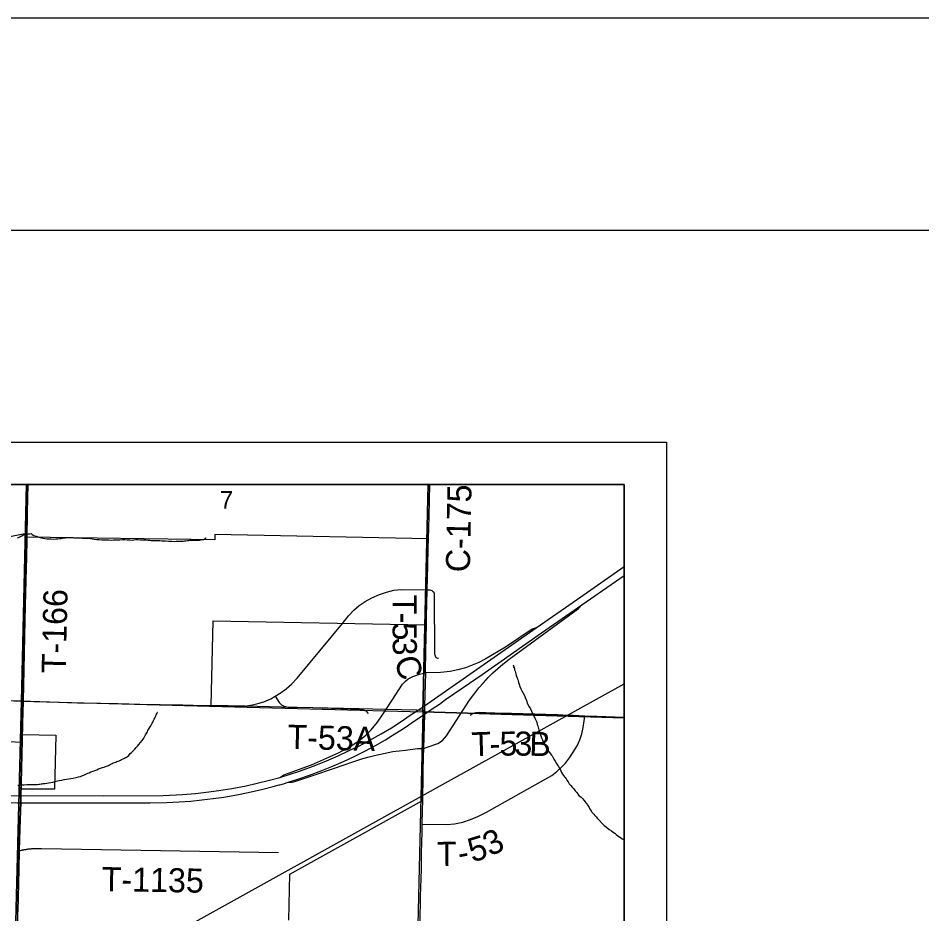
# Model space of a CAD drawing. Extents: x 0 to 34, y 0 to 22.
# Drawn here: x 7.471 to 9.602, y 19.887 to 22 of the extents above; entities that cross this region are included whole.
import ezdxf

# ---------------------------------------------------------------- set-up
doc = ezdxf.new("R2010")
doc.units = 0
for name, color, linetype in [('Default', 7, 'Continuous'), ('GM_X_City_Street', 7, 'Continuous'), ('GM_X_County_Road', 7, 'Continuous'), ('GM_X_County_Road_Text', 7, 'Continuous'), ('GM_X_Interchange_Ramps', 7, 'Continuous'), ('GM_X_Minor_River', 7, 'Continuous'), ('GM_X_Rail_Line', 7, 'Continuous'), ('GM_X_Section', 7, 'Continuous'), ('GM_X_Section_Text', 7, 'Continuous'), ('GM_X_State_Route', 7, 'Continuous'), ('GM_X_Township_Road', 7, 'Continuous'), ('GM_X_Township_Road_Text', 7, 'Continuous'), ('GM_X_US_Route', 7, 'Continuous'), ('SH_Border', 7, 'Continuous'), ('SH_Cut_Line', 7, 'Continuous'), ('SH_Data', 7, 'Continuous')]:
    doc.layers.add(name, color=color, linetype=linetype)

msp = doc.modelspace()

# ---------------------------------------------------------------- linework, layer by layer
at = {"layer": 'Default'}
for points in [[(7.4909, 20.9), (6.494, 20.9), (6.4853, 20.433), (7.4792, 20.3884)], [(8.4378, 20.9), (7.4909, 20.9), (7.4792, 20.3884), (8.425, 20.3637)], [(8.9, 20.3497), (8.9, 20.9), (8.4378, 20.9), (8.425, 20.3637)], [(8.9, 19.3466), (8.9, 20.3497), (8.425, 20.3637), (8.4018, 19.3591)]]:
    msp.add_lwpolyline(points, close=True, dxfattribs=at)
for points in [[(8.1092, 19.8726), (8.1117, 19.9804), (8.4242, 20.1544), (8.4244, 20.1687), (8.4248, 20.1996), (8.4253, 20.2288), (8.4259, 20.2469), (8.4287, 20.3585), (8.4289, 20.3671), (8.4123, 20.3673), (8.3381, 20.3691), (8.2755, 20.3708), (8.0918, 20.3747), (8.0063, 20.3766), (7.9263, 20.3784), (7.9309, 20.578), (8.4317, 20.5692), (8.4382, 20.7718), (7.935, 20.7816), (7.9348, 20.7695), (7.491, 20.7754), (7.491, 20.7842), (7.419, 20.7702)], [(7.3521, 20.3956), (7.4824, 20.3891), (7.4824, 20.3889), (7.4808, 20.31), (7.5596, 20.3083), (7.5569, 20.1815), (7.4776, 20.1816), (7.4779, 20.1915), (7.4782, 20.2008), (7.4786, 20.2232), (7.4804, 20.2916), (7.3464, 20.2972)]]:
    msp.add_lwpolyline(points, dxfattribs=at)
at = {"layer": 'GM_X_City_Street'}
msp.add_lwpolyline([(7.4738, 20.0361), (7.4792, 20.0373), (7.4804, 20.0376), (7.4816, 20.0379), (7.4829, 20.0381), (7.4841, 20.0384), (7.4853, 20.0386), (7.4865, 20.0388), (7.4877, 20.039), (7.4889, 20.0392), (7.4895, 20.0393), (7.4908, 20.0395), (7.492, 20.0397), (7.4932, 20.0399), (7.4944, 20.0401), (7.4957, 20.0402), (7.4969, 20.0403), (7.4981, 20.0405), (7.4993, 20.0406), (7.5006, 20.0407), (7.5018, 20.0408), (7.503, 20.0409), (7.5043, 20.041), (7.5055, 20.0411), (7.5061, 20.0411), (7.5073, 20.0412), (7.508, 20.0412), (7.5092, 20.0413), (7.5098, 20.0413), (7.5111, 20.0413), (7.5123, 20.0413), (7.5129, 20.0413), (7.5141, 20.0414), (7.5154, 20.0414), (7.5166, 20.0413), (7.5172, 20.0413), (7.5185, 20.0413), (7.5197, 20.0413), (7.5209, 20.0412), (7.5216, 20.0412), (7.5228, 20.0412), (7.5234, 20.0411), (7.5246, 20.0411), (7.5259, 20.041), (7.6676, 20.0386), (8.0853, 20.0316)], dxfattribs=at)
at = {"layer": 'GM_X_County_Road'}
for points in [[(8.4388, 20.7716), (8.44, 20.8244), (8.4418, 20.9)], [(8.4359, 20.6517), (8.4373, 20.7087), (8.4383, 20.7498), (8.4388, 20.7716)], [(8.2356, 20.5721), (8.2502, 20.5897), (8.2626, 20.6033), (8.2751, 20.6142), (8.2896, 20.6241), (8.3047, 20.6326), (8.3228, 20.6405), (8.3395, 20.6461), (8.357, 20.6504), (8.3744, 20.6523), (8.4359, 20.6517)], [(8.434, 20.5677), (8.4344, 20.5875), (8.4359, 20.6517)], [(7.9262, 20.3785), (7.9933, 20.3768), (8.0098, 20.3781), (8.0236, 20.3804), (8.0364, 20.3834), (8.0502, 20.3876), (8.0666, 20.3942), (8.0772, 20.4005), (8.091, 20.409), (8.1031, 20.4179), (8.1156, 20.4291), (8.1288, 20.4432), (8.2356, 20.5721)], [(8.4316, 20.4557), (8.4326, 20.5092), (8.434, 20.5677)], [(7.3527, 20.3949), (7.3686, 20.3941), (7.4177, 20.3919), (7.4532, 20.3906), (7.478, 20.3895), (7.4826, 20.3893)], [(7.4826, 20.3893), (7.5004, 20.3887), (7.5445, 20.3869), (7.5873, 20.3859), (7.611, 20.3852), (7.6248, 20.3848)], [(7.6248, 20.3848), (7.7061, 20.3829), (7.7577, 20.3818), (7.8062, 20.3809), (7.859, 20.3798), (7.9081, 20.3789), (7.9262, 20.3785)]]:
    msp.add_lwpolyline(points, dxfattribs=at)
at = {"layer": 'GM_X_Interchange_Ramps'}
for points in [[(8.4267, 20.2774), (8.4402, 20.2821), (8.4609, 20.2893), (8.4721, 20.2959), (8.4813, 20.3068), (8.5355, 20.3913), (8.5454, 20.4047), (8.5575, 20.4199), (8.5681, 20.4324), (8.5792, 20.4445), (8.5908, 20.456), (8.6019, 20.4662), (8.6141, 20.4764), (8.6289, 20.4876), (8.7922, 20.6077), (8.8006, 20.6163)], [(8.6929, 20.5615), (8.6832, 20.5587), (8.6202, 20.5162), (8.572, 20.4879), (8.5575, 20.48), (8.5421, 20.4735), (8.5257, 20.4675), (8.5076, 20.4626), (8.4895, 20.459), (8.4668, 20.4564), (8.4316, 20.4557)]]:
    msp.add_lwpolyline(points, dxfattribs=at)
at = {"layer": 'GM_X_Minor_River'}
for points in [[(7.4697, 20.774), (7.4716, 20.7747), (7.4747, 20.7762), (7.4774, 20.778), (7.4797, 20.7791), (7.4832, 20.7812), (7.4863, 20.7823), (7.4909, 20.7829), (7.4943, 20.7836), (7.4985, 20.7838)], [(7.4985, 20.7838), (7.5015, 20.7841), (7.5037, 20.7822), (7.5082, 20.7798), (7.5131, 20.7777), (7.5184, 20.7764), (7.5229, 20.7751), (7.5263, 20.7743), (7.5289, 20.7735), (7.5339, 20.7726), (7.5384, 20.772), (7.5429, 20.7715), (7.5483, 20.7714), (7.5539, 20.7712), (7.5597, 20.7714), (7.5642, 20.7717), (7.5684, 20.7723), (7.5726, 20.7726), (7.5757, 20.7733), (7.5791, 20.7739), (7.5829, 20.7742), (7.5958, 20.7746), (7.5996, 20.7745), (7.6034, 20.7744), (7.6076, 20.7742), (7.6129, 20.7741), (7.6178, 20.7739), (7.6231, 20.7734), (7.6281, 20.7733), (7.6326, 20.7735), (7.6372, 20.773), (7.6413, 20.7725), (7.6455, 20.7716), (7.65, 20.7711), (7.6561, 20.7702), (7.6622, 20.77), (7.6682, 20.7694), (7.6739, 20.7693), (7.6796, 20.7691), (7.6849, 20.769), (7.6902, 20.7688), (7.696, 20.7694), (7.7043, 20.7695), (7.7108, 20.7697), (7.7172, 20.7699), (7.7222, 20.7702), (7.7282, 20.7696), (7.7343, 20.7691), (7.74, 20.7689), (7.7438, 20.7692), (7.7488, 20.7702), (7.7529, 20.77), (7.7594, 20.7695), (7.7662, 20.7693), (7.7723, 20.7691), (7.7776, 20.7689), (7.7818, 20.7684), (7.7844, 20.768), (7.7882, 20.7675), (7.7909, 20.7674), (7.7939, 20.7677), (7.7996, 20.7676), (7.8049, 20.7674), (7.8095, 20.7673), (7.8129, 20.7672), (7.8159, 20.7667), (7.8182, 20.7666), (7.8254, 20.766), (7.8292, 20.7663), (7.8337, 20.7662), (7.8398, 20.7656), (7.8436, 20.7659), (7.8474, 20.7662), (7.8516, 20.7661), (7.8565, 20.7663), (7.8603, 20.7662), (7.8634, 20.7669), (7.8668, 20.7671), (7.8702, 20.7678), (7.8733, 20.7681), (7.876, 20.7684), (7.8786, 20.7683), (7.8813, 20.7686), (7.884, 20.7689), (7.8862, 20.7689), (7.89, 20.7687), (7.8919, 20.7687), (7.8942, 20.7686), (7.8965, 20.7689), (7.8988, 20.7689), (7.9018, 20.7692), (7.9053, 20.7698), (7.9079, 20.7705), (7.9102, 20.7716), (7.913, 20.7734), (7.9137, 20.7738), (7.9137, 20.7734)], [(8.6381, 20.4746), (8.6405, 20.4681), (8.6395, 20.4708), (8.6405, 20.4681), (8.6416, 20.4658), (8.6419, 20.4627), (8.6429, 20.4596), (8.6436, 20.4566), (8.6446, 20.4531), (8.6457, 20.4497), (8.6467, 20.4455), (8.6481, 20.4428), (8.6492, 20.4401), (8.6502, 20.4366), (8.6513, 20.4332), (8.6523, 20.4286), (8.654, 20.4236), (8.6562, 20.4182), (8.659, 20.4128), (8.6619, 20.4074), (8.6648, 20.4024), (8.667, 20.3978), (8.6698, 20.3904), (8.6726, 20.3828), (8.6758, 20.3758), (8.6791, 20.3704), (8.6816, 20.3654), (8.6841, 20.3596), (8.6869, 20.3538), (8.6895, 20.3488), (8.6916, 20.3442), (8.6934, 20.3411), (8.6941, 20.3384), (8.6951, 20.3338), (8.6965, 20.3304), (8.6972, 20.3273), (8.6979, 20.3243), (8.6989, 20.3208), (8.7003, 20.317), (8.7017, 20.3127), (8.7034, 20.3074), (8.7056, 20.3024), (8.7077, 20.2974), (8.7095, 20.2928), (8.7113, 20.2893), (8.7127, 20.2866), (8.7138, 20.2843), (8.7145, 20.2823), (8.7163, 20.2789), (8.7196, 20.2742), (8.7232, 20.2688), (8.7265, 20.2645), (8.7291, 20.2618), (8.7305, 20.2598), (8.732, 20.2564), (8.7345, 20.2521), (8.7374, 20.2471), (8.7403, 20.2421), (8.7432, 20.2378), (8.7457, 20.2343), (8.7472, 20.2316), (8.749, 20.2285), (8.7508, 20.2247), (8.7526, 20.2208), (8.7551, 20.2169), (8.7573, 20.2138), (8.7595, 20.2107), (8.7613, 20.2084), (8.7631, 20.2057), (8.7653, 20.2026), (8.7679, 20.1983), (8.7708, 20.1941), (8.7741, 20.1902), (8.7774, 20.1859), (8.7811, 20.182), (8.7847, 20.1773), (8.7884, 20.173), (8.7928, 20.1672), (8.7987, 20.1625), (8.8024, 20.1586), (8.8053, 20.155), (8.8079, 20.1516), (8.8101, 20.1492), (8.8119, 20.1465), (8.8134, 20.1446), (8.8148, 20.1426), (8.8159, 20.1403), (8.8174, 20.1376), (8.8195, 20.1341), (8.8225, 20.1302), (8.8243, 20.1271), (8.8265, 20.1244), (8.8287, 20.1221), (8.8313, 20.1193), (8.8342, 20.1158), (8.8375, 20.1119), (8.8534, 20.0959), (8.8589, 20.0915), (8.8645, 20.0861), (8.8705, 20.0828), (8.8746, 20.0801)], [(7.6288, 20.2157), (7.6319, 20.2171), (7.635, 20.2186), (7.6388, 20.22), (7.6427, 20.2221), (7.6481, 20.2235), (7.6519, 20.2253), (7.6565, 20.227), (7.6607, 20.2288), (7.6654, 20.2306), (7.6696, 20.232), (7.6738, 20.2334), (7.6769, 20.2344), (7.6792, 20.2351), (7.6815, 20.2362), (7.6838, 20.2373), (7.6861, 20.2384), (7.6892, 20.2402), (7.6923, 20.2416), (7.6953, 20.243), (7.6984, 20.2441), (7.7011, 20.2451), (7.7038, 20.2462), (7.7065, 20.2469), (7.7088, 20.248), (7.7107, 20.2487), (7.7126, 20.2498), (7.715, 20.2512), (7.7188, 20.2526), (7.7215, 20.2541), (7.7242, 20.2559), (7.7265, 20.257), (7.7285, 20.2584), (7.7316, 20.261), (7.7335, 20.2628), (7.7355, 20.2651), (7.7382, 20.2676), (7.7414, 20.271), (7.7461, 20.2758), (7.7496, 20.2795), (7.7527, 20.2828), (7.7559, 20.2865), (7.7638, 20.2962), (7.7657, 20.2991), (7.767, 20.3018), (7.7686, 20.3044), (7.7698, 20.3066), (7.7714, 20.3096), (7.7729, 20.3115), (7.7741, 20.3137), (7.7757, 20.3163), (7.777, 20.3193), (7.7786, 20.3223), (7.7806, 20.3257), (7.7822, 20.3283), (7.7838, 20.3309), (7.7854, 20.3335), (7.787, 20.3365), (7.7886, 20.3395), (7.7902, 20.3433), (7.7918, 20.3463), (7.793, 20.3489), (7.7942, 20.3512), (7.7955, 20.3538), (7.7963, 20.356), (7.7971, 20.3579), (7.7987, 20.3605), (7.7995, 20.362), (7.7991, 20.362)], [(7.4701, 20.1906), (7.4735, 20.1909), (7.4766, 20.1912), (7.4804, 20.1915), (7.4849, 20.1917), (7.4918, 20.1919), (7.4971, 20.1921), (7.5032, 20.192), (7.5089, 20.1922), (7.5134, 20.192), (7.5165, 20.1923), (7.5195, 20.193), (7.5222, 20.1933), (7.5249, 20.1936), (7.5275, 20.1939), (7.5302, 20.1942), (7.5336, 20.1949), (7.5386, 20.1955), (7.5428, 20.1961), (7.5481, 20.1971), (7.5531, 20.1981), (7.5577, 20.1995), (7.5634, 20.2005), (7.5688, 20.2018), (7.5738, 20.2028), (7.5791, 20.2042), (7.6009, 20.2074), (7.6077, 20.2087), (7.6135, 20.21), (7.6181, 20.2111), (7.6215, 20.2125), (7.6238, 20.2132), (7.6261, 20.2146), (7.6288, 20.2157)], [(8.8746, 20.0801), (8.8783, 20.0773), (8.8816, 20.0745), (8.8846, 20.0722), (8.8879, 20.0698), (8.8916, 20.067), (8.8957, 20.0642), (8.9, 20.0615)]]:
    msp.add_lwpolyline(points, dxfattribs=at)
at = {"layer": 'GM_X_Rail_Line'}
msp.add_lwpolyline([(6.8451, 19.2922), (7.7668, 19.8007), (8.4856, 20.1997), (8.9, 20.43)], dxfattribs=at)
at = {"layer": 'GM_X_Section'}
for points in [[(6.4853, 20.433), (7.4792, 20.3884), (7.4533, 19.3812), (6.7152, 19.4245), (6.466, 19.4302)], [(7.4792, 20.3884), (8.425, 20.3637), (8.4018, 19.3591), (7.4533, 19.3812)]]:
    msp.add_lwpolyline(points, close=True, dxfattribs=at)
at = {"layer": 'GM_X_State_Route'}
for p, q in [((8.3383, 20.3685), (8.353, 20.3912)), ((8.4267, 20.2774), (8.4263, 20.2574))]:
    msp.add_line(p, q, dxfattribs=at)
for points in [[(8.353, 20.3912), (8.3774, 20.4291), (8.3843, 20.436), (8.3908, 20.4416), (8.4017, 20.4468), (8.4175, 20.4521), (8.4316, 20.4557), (8.4293, 20.3781), (8.4291, 20.3665), (8.4289, 20.358), (8.4267, 20.2774)], [(8.0884, 20.2091), (8.0972, 20.2153), (8.1084, 20.219), (8.1626, 20.2387), (8.1913, 20.2512), (8.2261, 20.2666), (8.2554, 20.2824), (8.2754, 20.2959), (8.2902, 20.3081), (8.3037, 20.3212), (8.3182, 20.3393), (8.329, 20.3541), (8.3383, 20.3685)], [(8.2506, 20.2424), (8.2652, 20.2473), (8.2841, 20.2532), (8.2989, 20.2576), (8.3148, 20.2611), (8.3365, 20.266), (8.355, 20.2697), (8.3845, 20.2735), (8.4128, 20.2771), (8.4267, 20.2774)], [(8.4263, 20.2574), (8.4261, 20.2464), (8.4257, 20.2323)], [(8.1728, 20.2161), (8.2467, 20.2411), (8.2506, 20.2424)], [(8.4257, 20.2323), (8.4255, 20.2282), (8.425, 20.199), (8.4246, 20.1682), (8.4245, 20.1539)], [(8.1077, 20.1974), (8.1171, 20.1981), (8.1236, 20.1995), (8.1728, 20.2161)], [(8.4245, 20.1539), (8.424, 20.1325), (8.4233, 20.0988), (8.4229, 20.0796), (8.4218, 20.031), (8.4212, 19.9931), (8.4205, 19.9695), (8.4193, 19.929), (8.418, 19.8657)]]:
    msp.add_lwpolyline(points, dxfattribs=at)
at = {"layer": 'GM_X_Township_Road'}
for p, q in [((7.4937, 20.8873), (7.4939, 20.9)), ((7.4915, 20.7747), (7.4917, 20.7837)), ((7.4806, 20.2911), (7.481, 20.3109))]:
    msp.add_line(p, q, dxfattribs=at)
for points in [[(7.4703, 19.8915), (7.471, 19.9276), (7.4718, 19.9568), (7.4728, 19.9942), (7.4735, 20.0366), (7.4749, 20.0879), (7.4763, 20.1302), (7.4769, 20.1497), (7.477, 20.1571), (7.4773, 20.1668), (7.4779, 20.1915), (7.4782, 20.2008), (7.4786, 20.2232), (7.4798, 20.2686), (7.4804, 20.2916), (7.4813, 20.3401), (7.4823, 20.3865), (7.4824, 20.3899), (7.4841, 20.4627), (7.4861, 20.5422), (7.4875, 20.6143), (7.4883, 20.6429), (7.4889, 20.6746), (7.4903, 20.728), (7.4912, 20.7703), (7.4924, 20.8349), (7.4937, 20.9), (2.1, 20.9)], [(8.9, 16.335), (8.9, 20.9), (7.4937, 20.9), (7.4924, 20.8349), (7.4912, 20.7703), (7.4903, 20.728), (7.4889, 20.6746), (7.4883, 20.6429), (7.4875, 20.6143), (7.4861, 20.5422), (7.4841, 20.4627), (7.4824, 20.3899), (7.4823, 20.3865), (7.4813, 20.3401), (7.4804, 20.2916), (7.4798, 20.2686), (7.4786, 20.2232), (7.4782, 20.2008), (7.4779, 20.1915), (7.4773, 20.1668), (7.477, 20.1571), (7.4769, 20.1497), (7.4763, 20.1302), (7.4749, 20.0879), (7.4735, 20.0366), (7.4728, 19.9942), (7.4718, 19.9568), (7.471, 19.9276), (7.4703, 19.8915)], [(7.4917, 20.7837), (7.4927, 20.8344), (7.4937, 20.8873)], [(7.4826, 20.3893), (7.4843, 20.4621), (7.4864, 20.5417), (7.4877, 20.6138), (7.4885, 20.6423), (7.4891, 20.6741), (7.4905, 20.7275), (7.4915, 20.7698), (7.4915, 20.7747)], [(8.4359, 20.6517), (8.4417, 20.651), (8.4469, 20.6496), (8.45, 20.6465), (8.4521, 20.6434), (8.4521, 20.6399), (8.4528, 20.5001), (8.4541, 20.4956), (8.4559, 20.4921), (8.4597, 20.4904), (8.4625, 20.4904)], [(8.0772, 20.4005), (8.0864, 20.386), (8.092, 20.3801), (8.0985, 20.3768), (8.1068, 20.3748), (8.1077, 20.3748)], [(7.481, 20.3109), (7.4815, 20.3395), (7.4825, 20.3859), (7.4826, 20.3893)], [(8.1077, 20.3748), (8.1663, 20.3735), (8.2758, 20.3702)], [(8.2758, 20.3702), (8.2846, 20.3686), (8.2912, 20.3659), (8.2968, 20.3594)], [(8.5372, 20.3558), (8.5441, 20.3604), (8.5506, 20.3623), (8.5585, 20.3627), (8.5738, 20.3622), (8.595, 20.3615), (8.6341, 20.3602), (8.7429, 20.3572), (8.769, 20.356)], [(8.4233, 20.0988), (8.4816, 20.0976), (8.5003, 20.0997), (8.5194, 20.1035), (8.5381, 20.1097), (8.5548, 20.1167), (8.5752, 20.1271), (8.7158, 20.2052), (8.7293, 20.2135), (8.7414, 20.2229), (8.7525, 20.2333), (8.7619, 20.2426), (8.7713, 20.2548), (8.7803, 20.2683), (8.789, 20.2832), (8.7956, 20.2978), (8.8001, 20.3117), (8.8035, 20.3266), (8.806, 20.3426), (8.8077, 20.3544)], [(8.769, 20.356), (8.7801, 20.3555), (8.8077, 20.3544)], [(8.8077, 20.3544), (8.8354, 20.3533), (8.9, 20.3512)], [(7.4771, 20.1491), (7.4773, 20.1565), (7.4775, 20.1663), (7.4782, 20.1909), (7.4785, 20.2002), (7.4788, 20.2226), (7.48, 20.2681), (7.4806, 20.2911)], [(7.4738, 20.0361), (7.4752, 20.0874), (7.4765, 20.1296), (7.4771, 20.1491)], [(7.4656, 19.6941), (7.4656, 19.6952), (7.4663, 19.7157), (7.4669, 19.7399), (7.4675, 19.7642), (7.4683, 19.8002), (7.4687, 19.8238), (7.4693, 19.8487), (7.4701, 19.8761), (7.4705, 19.891), (7.4712, 19.927), (7.472, 19.9562), (7.473, 19.9936), (7.4738, 20.0361)]]:
    msp.add_lwpolyline(points, dxfattribs=at)
at = {"layer": 'GM_X_US_Route'}
for p, q in [((8.7898, 20.6293), (8.9, 20.7065)), ((8.6929, 20.5615), (8.7898, 20.6293))]:
    msp.add_line(p, q, dxfattribs=at)
for points in [[(8.8006, 20.6163), (8.8797, 20.6713), (8.9, 20.6855)], [(8.4289, 20.358), (8.443, 20.3675), (8.4561, 20.3759), (8.4645, 20.382), (8.479, 20.3926), (8.5355, 20.4313), (8.5652, 20.4518), (8.705, 20.5501), (8.8006, 20.6163)], [(8.4125, 20.3668), (8.4293, 20.3781), (8.6929, 20.5615)], [(6.9763, 20.1652), (7.4775, 20.1663), (7.6711, 20.1653), (7.8132, 20.1663), (7.8585, 20.1687), (7.8894, 20.1713), (7.9147, 20.1739), (7.9443, 20.1779), (7.9749, 20.1825), (8.0091, 20.1894), (8.0347, 20.1953), (8.0637, 20.2025), (8.0884, 20.2091), (8.1127, 20.2167), (8.1324, 20.2232), (8.1521, 20.2301), (8.1689, 20.2364), (8.1985, 20.2482), (8.2255, 20.2601), (8.2534, 20.2729), (8.2758, 20.2837), (8.3007, 20.2969), (8.3271, 20.312), (8.3514, 20.3262), (8.3741, 20.3406), (8.3958, 20.3554), (8.4125, 20.3668)], [(8.1077, 20.1974), (8.1308, 20.2047), (8.1584, 20.2143), (8.1869, 20.2251), (8.211, 20.2349), (8.2384, 20.2468), (8.2615, 20.2576), (8.2888, 20.2712), (8.3135, 20.2843), (8.3373, 20.2978), (8.3532, 20.3075), (8.3794, 20.3242), (8.3921, 20.3327), (8.4037, 20.3405), (8.417, 20.3497), (8.4289, 20.358)], [(7.6698, 20.149), (7.6708, 20.149), (7.7826, 20.1493), (7.8205, 20.1501), (7.8509, 20.1514), (7.8782, 20.1532), (7.9041, 20.1557), (7.9306, 20.1589), (7.9564, 20.1627), (7.9864, 20.1679), (8.0138, 20.1734), (8.0447, 20.1804), (8.0724, 20.1874), (8.0868, 20.1912), (8.0878, 20.1915)], [(8.0878, 20.1915), (8.0965, 20.1939), (8.1077, 20.1974)], [(6.9756, 20.1488), (6.9765, 20.1488), (6.9918, 20.1488), (7.021, 20.149), (7.0788, 20.1493), (7.1179, 20.1488), (7.1847, 20.1488), (7.2953, 20.1491), (7.4457, 20.1494), (7.4689, 20.1492), (7.4771, 20.1491)], [(7.4771, 20.1491), (7.6222, 20.1493), (7.6698, 20.149)]]:
    msp.add_lwpolyline(points, dxfattribs=at)
at = {"layer": 'SH_Border'}
msp.add_lwpolyline([(1.5, 21.5), (33.5, 21.5), (33.5, 0.5), (1.5, 0.5)], close=True, dxfattribs=at)
at = {"layer": 'SH_Cut_Line'}
msp.add_lwpolyline([(0, 0), (34, 0), (34, 22), (0, 22)], close=True, dxfattribs=at)
at = {"layer": 'SH_Data'}
for p, q in [((2, 21), (9, 21)), ((9, 21), (9, 14)), ((2.1, 20.9), (8.9, 20.9)), ((8.9, 20.9), (8.9, 14.1))]:
    msp.add_line(p, q, dxfattribs=at)

# ---------------------------------------------------------------- texts
at = {"layer": 'GM_X_County_Road_Text'}
msp.add_text('C-175', height=0.05682, rotation=88.8984, dxfattribs=at).set_placement((8.5363, 20.6925))
at = {"layer": 'GM_X_Section_Text'}
msp.add_text('7', height=0.0419, rotation=0, dxfattribs=at).set_placement((7.9468, 20.8425))
at = {"layer": 'GM_X_Township_Road_Text'}
for s, height, rotation, p in [('T-166', 0.05682, 88.5955, (7.5829, 20.4541)), ('T', 0.0568, 270.0064, (8.3539, 20.6402)), ('-', 0.0568, 270.0505, (8.3539, 20.5977)), ('5', 0.0568, 270.2365, (8.3539, 20.5742)), ('3', 0.0568, 271.0412, (8.3541, 20.5383)), ('C', 0.0568, 286.8415, (8.3574, 20.4865)), ('T-53A', 0.05682, 358.4517, (8.1056, 20.2766)), ('T', 0.0568, 1.9074, (8.541, 20.2584)), ('5', 0.0568, 0.3122, (8.6064, 20.2603)), ('3', 0.0568, 359.4744, (8.6412, 20.2605)), ('B', 0.0568, 358.5519, (8.6759, 20.2602)), ('-', 0.0568, 1.3505, (8.5833, 20.2598)), ('3', 0.0568, 25.9824, (8.5844, 20.0217)), ('5', 0.0568, 17.1989, (8.5421, 20.0079)), ('T', 0.0568, 0.7243, (8.4592, 20)), ('-', 0.0568, 11.1567, (8.5129, 20.0017)), ('T-1135', 0.05682, 359.0643, (7.6677, 19.9408))]:
    msp.add_text(s, height=height, rotation=rotation, dxfattribs=at).set_placement(p)

doc.saveas('drawing.dxf')
